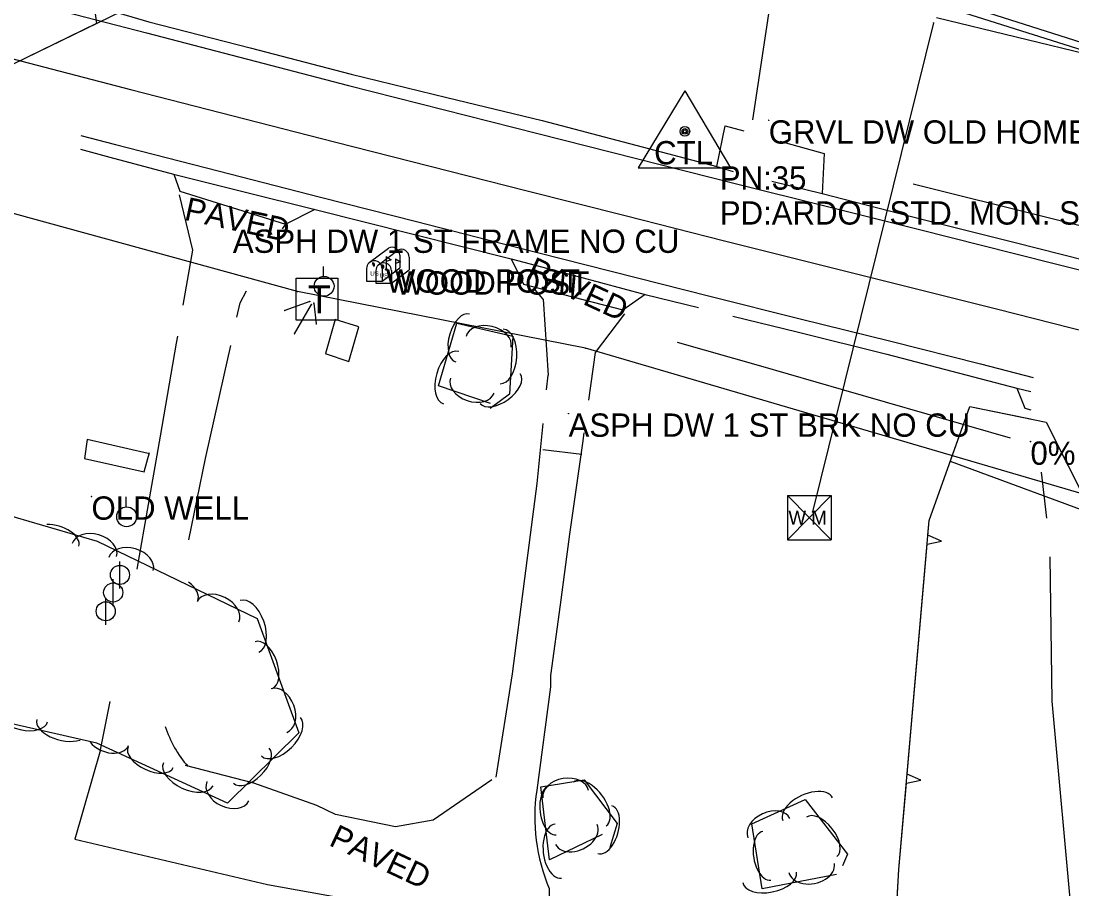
# Model space of a CAD drawing. Extents: x 954793 to 988390, y 1867850 to 1924428.
# Drawn here: x 963576.6 to 963802.1, y 1900745.2 to 1900931.5 of the extents above; entities that cross this region are included whole.
import ezdxf

# ---------------------------------------------------------------- set-up
doc = ezdxf.new("R2010")
doc.units = 0
for name, color, linetype in [('S_CROSS_DRAIN_ANNOT', 7, 'Continuous'), ('S_DITCHLINE', 7, 'Continuous'), ('S_DRG_PT_SYM', 7, 'Continuous'), ('S_DRIVEWAY', 7, 'Continuous'), ('S_EDGE_BITUMINOUS', 7, 'Continuous'), ('S_EDGE_PAVEMENT', 7, 'Continuous'), ('S_FIBER_OPTIC_CABLE', 7, 'Continuous'), ('S_MAILBOX', 7, 'Continuous'), ('S_MAILBOX_ANNOT', 7, 'Continuous'), ('S_MISC_STRUCTURES', 7, 'Continuous'), ('S_MSC_PT_SYM', 7, 'Continuous'), ('S_PARKING', 7, 'Continuous'), ('S_PARKING_ANNOT', 7, 'Continuous'), ('S_PAVEMENT_CROWN', 7, 'Continuous'), ('S_PRIMARY_CTL', 7, 'Continuous'), ('S_PRIMARY_CTL_ANNOT', 7, 'Continuous'), ('S_SHOULDER', 7, 'Continuous'), ('S_SIDEWALK', 7, 'Continuous'), ('S_STREAM', 7, 'Continuous'), ('S_SURVEY_TEXT_ANNOT', 7, 'Continuous'), ('S_TELEPHONE_UTILITIES', 7, 'Continuous'), ('S_TRAILS', 7, 'Continuous'), ('S_TREE', 7, 'Continuous'), ('S_UTILITY_POLE', 7, 'Continuous'), ('S_UTL_PT_SYM', 7, 'Continuous'), ('S_WATER_UTILITIES', 7, 'Continuous')]:
    doc.layers.add(name, color=color, linetype=linetype)

msp = doc.modelspace()

# ---------------------------------------------------------------- linework, layer by layer
at = {"layer": 'S_DITCHLINE'}
msp.add_lwpolyline([(963788.94, 1900841.95), (963771.08, 1900847.1), (963753.21, 1900852.24), (963735.35, 1900857.38), (963717.49, 1900862.52)], dxfattribs=at)
at = {"layer": 'S_DRG_PT_SYM'}
msp.add_lwpolyline([(963793.23, 1900841.24), (963793.23, 1900841.29), (963793.23, 1900841.24), (963793.18, 1900841.24), (963793.23, 1900841.24), (963793.23, 1900841.19), (963793.23, 1900841.24), (963793.28, 1900841.24)], dxfattribs=at)
at = {"layer": 'S_DRIVEWAY'}
for p, q in [((963678.6, 1900769.21), (963682.07, 1900791.4)), ((963689.94, 1900745.3), (963689.82, 1900732.7))]:
    msp.add_line(p, q, dxfattribs=at)
for points in [[(963610.53, 1900894.17), (963613.41, 1900882.29), (963611.35, 1900870.52)], [(963688.68, 1900871.79), (963686.96, 1900873.81)], [(963622.94, 1900867.95), (963623.61, 1900871)], [(963706.08, 1900868.66), (963699.83, 1900860.34), (963698.39, 1900850.13)], [(963610.18, 1900863.81), (963609.92, 1900862.34), (963606.43, 1900842.39), (963602.93, 1900822.45), (963601.43, 1900813.86)], [(963612.64, 1900820.11), (963616.22, 1900837.57), (963620.19, 1900855.49), (963621.59, 1900861.85)], [(963689.38, 1900852.32), (963689.7, 1900855.49)], [(963682.07, 1900791.4), (963684.71, 1900811.83), (963687.35, 1900832.26), (963688.65, 1900845.13)], [(963697.39, 1900843.07), (963697.08, 1900840.85), (963694.33, 1900821.36), (963692.3, 1900806.18), (963690.26, 1900791)], [(963690.26, 1900791), (963690.24, 1900788.61), (963687.26, 1900766.42)], [(963593.65, 1900775.09), (963588.15, 1900755.93), (963629.47, 1900746.18), (963651.41, 1900742.27), (963660.42, 1900737.2)], [(963677.61, 1900768.67), (963665.05, 1900760.02), (963656.93, 1900758.58), (963644.11, 1900761.23), (963640.08, 1900763.12), (963626.59, 1900767.94), (963611.88, 1900771.75)]]:
    msp.add_lwpolyline(points, dxfattribs=at)
msp.add_ellipse((963726.49, 1900760.74), major_axis=(-4.97, -39.48), ratio=0.996236, start_param=4.693811, end_param=5.23562, dxfattribs=at)
at = {"layer": 'S_EDGE_BITUMINOUS'}
for points in [[(963725.92, 1900900.28), (963727.72, 1900909), (963731.73, 1900907.87)], [(963739.46, 1900905.69), (963748.98, 1900903.01), (963748.52, 1900894.48)], [(963609.41, 1900898.64), (963610.67, 1900894.96), (963633.39, 1900887.86), (963639.69, 1900891.08)], [(963681.79, 1900880.42), (963684.46, 1900875.03), (963705.73, 1900869.47), (963710.56, 1900872.88)], [(963790.3, 1900852.69), (963792.05, 1900848.4), (963793.31, 1900848.06)]]:
    msp.add_lwpolyline(points, dxfattribs=at)
at = {"layer": 'S_EDGE_PAVEMENT'}
for points in [[(963564.17, 1900939.03), (963583.84, 1900933.98), (963603.52, 1900928.94), (963625.22, 1900923.29), (963646.91, 1900917.64), (963667.21, 1900912.48), (963687.51, 1900907.31), (963708.69, 1900901.95), (963729.87, 1900896.59), (963749.64, 1900891.65), (963769.42, 1900886.71), (963789.55, 1900881.66), (963809.68, 1900876.6)], [(963589.44, 1900906.92), (963596.89, 1900905), (963618.88, 1900899.33), (963640.86, 1900893.66), (963661.47, 1900888.43), (963682.07, 1900883.19), (963703.23, 1900877.82), (963724.39, 1900872.44), (963743.82, 1900867.6), (963763.24, 1900862.77), (963782.5, 1900857.88), (963793.84, 1900855)]]:
    msp.add_lwpolyline(points, dxfattribs=at)
at = {"layer": 'S_FIBER_OPTIC_CABLE'}
for p, q in [((964278.11, 1900775.13), (963743.78, 1900946.13)), ((964280.9, 1900773.98), (963742.61, 1900944.77)), ((963635.92, 1900873.41), (963480.96, 1900915.92)), ((963697.76, 1900861.28), (963635.92, 1900873.41)), ((963638.55, 1900871.29), (963633.18, 1900869.35)), ((963635.27, 1900864.38), (963638.94, 1900870.66)), ((963639.41, 1900870.93), (963639.97, 1900866.46)), ((963824.31, 1900824.17), (963697.76, 1900861.28)), ((963828.41, 1900817.62), (963776.07, 1900836.95))]:
    msp.add_line(p, q, dxfattribs=at)
at = {"layer": 'S_MAILBOX'}
for p, q in [((963651.32, 1900879.62), (963655.45, 1900882.73)), ((963653.33, 1900879.18), (963657.46, 1900882.29)), ((963654.93, 1900880.91), (963654.93, 1900878.19)), ((963656.94, 1900880.47), (963656.94, 1900877.76)), ((963657.88, 1900881.25), (963657.88, 1900878.54)), ((963659.89, 1900880.82), (963659.89, 1900878.1)), ((963650.76, 1900878.35), (963650.76, 1900875.63)), ((963652.77, 1900877.91), (963652.77, 1900875.19)), ((963654.09, 1900875.63), (963657.88, 1900878.54)), ((963654.09, 1900878.35), (963654.09, 1900875.63)), ((963656.1, 1900875.19), (963659.89, 1900878.1)), ((963656.1, 1900877.91), (963656.1, 1900875.19)), ((963650.76, 1900875.63), (963654.09, 1900875.63)), ((963652.77, 1900875.19), (963656.1, 1900875.19))]:
    msp.add_line(p, q, dxfattribs=at)
for points in [[(963654.93, 1900880.91), (963656.04, 1900880.24), (963654.93, 1900879.9)], [(963656.94, 1900880.47), (963658.05, 1900879.81), (963656.94, 1900879.46)], [(963651.95, 1900879.46), (963652.17, 1900879.32), (963652.17, 1900878.93), (963652.47, 1900878.93), (963652.47, 1900879.29), (963652.28, 1900879.54), (963651.95, 1900879.49)], [(963653.96, 1900879.02), (963654.18, 1900878.88), (963654.18, 1900878.5), (963654.48, 1900878.5), (963654.48, 1900878.86), (963654.29, 1900879.11), (963653.96, 1900879.05)]]:
    msp.add_lwpolyline(points, dxfattribs=at)
for centre, end in [((963656.22, 1900881.25), 117.5718), ((963658.23, 1900880.82), 117.5718), ((963652.43, 1900878.35), 180), ((963654.43, 1900877.91), 180)]:
    msp.add_arc(centre, 1.66, 0, end, dxfattribs=at)
for centre in [(963654.93, 1900878.19), (963656.94, 1900877.76)]:
    msp.add_ellipse(centre, major_axis=(0.145, 0.132), ratio=0.564646, dxfattribs=at)
at = {"layer": 'S_MISC_STRUCTURES'}
msp.add_lwpolyline([(963641.88, 1900860.14), (963646.98, 1900858.4), (963649.08, 1900865.85), (963643.99, 1900867.42), (963641.95, 1900860.14)], dxfattribs=at)
at = {"layer": 'S_MSC_PT_SYM'}
for points in [[(963737.06, 1900910.16), (963737.06, 1900910.21), (963737.06, 1900910.16), (963737.01, 1900910.16), (963737.06, 1900910.16), (963737.06, 1900910.11), (963737.06, 1900910.16), (963737.11, 1900910.16)], [(963622.05, 1900886.72), (963622.05, 1900886.77), (963622.05, 1900886.72), (963622, 1900886.72), (963622.05, 1900886.72), (963622.05, 1900886.67), (963622.05, 1900886.72), (963622.1, 1900886.72)], [(963694.11, 1900847.26), (963694.11, 1900847.31), (963694.11, 1900847.26), (963694.06, 1900847.26), (963694.11, 1900847.26), (963694.11, 1900847.21), (963694.11, 1900847.26), (963694.16, 1900847.26)], [(963591.72, 1900829.46), (963591.72, 1900829.51), (963591.72, 1900829.46), (963591.67, 1900829.46), (963591.72, 1900829.46), (963591.72, 1900829.41), (963591.72, 1900829.46), (963591.77, 1900829.46)]]:
    msp.add_lwpolyline(points, dxfattribs=at)
at = {"layer": 'S_PARKING'}
for p, q in [((963633.39, 1900887.86), (963632.67, 1900886.9)), ((963623.61, 1900871), (963625, 1900873.54)), ((963688.68, 1900871.79), (963689.7, 1900855.49)), ((963796.77, 1900824.76), (963795.63, 1900834.66))]:
    msp.add_line(p, q, dxfattribs=at)
for points in [[(963696.92, 1900838.42), (963688.58, 1900839.49)], [(963810.2, 1900814.41), (963810.2, 1900813.25), (963812.44, 1900775.03), (963816.58, 1900735.43), (963822.8, 1900714.82), (963834.09, 1900691.03), (963833.12, 1900680.93), (963807.8, 1900685.36), (963810.33, 1900704.24), (963802.22, 1900737.62), (963797.92, 1900785.51), (963797.43, 1900816.5)], [(963593.65, 1900775.09), (963595.76, 1900785.48)]]:
    msp.add_lwpolyline(points, dxfattribs=at)
msp.add_ellipse((963630.03, 1900787.22), major_axis=(13.66, -19.28), ratio=0.997823, start_param=4.403502, end_param=4.825122, dxfattribs=at)
at = {"layer": 'S_PAVEMENT_CROWN'}
msp.add_lwpolyline([(963559.23, 1900927.43), (963579.79, 1900922.06), (963600.35, 1900916.69), (963622.13, 1900911.12), (963643.9, 1900905.56), (963664.4, 1900900.33), (963684.9, 1900895.11), (963706.23, 1900889.71), (963727.56, 1900884.31), (963746.73, 1900879.52), (963765.9, 1900874.72), (963785.91, 1900869.69), (963805.93, 1900864.66)], dxfattribs=at)
msp.add_lwpolyline([(963559.23, 1900927.43), (963579.79, 1900922.06), (963600.35, 1900916.69), (963622.13, 1900911.12), (963643.9, 1900905.56), (963664.4, 1900900.33), (963684.9, 1900895.11), (963706.23, 1900889.71), (963727.56, 1900884.31), (963746.73, 1900879.52), (963765.9, 1900874.72), (963785.91, 1900869.69), (963805.93, 1900864.66)], dxfattribs=at)
at = {"layer": 'S_PRIMARY_CTL'}
for p, q in [((963719.06, 1900916.49), (963709.02, 1900899.98)), ((963719.06, 1900916.49), (963728.88, 1900899.98)), ((963709.02, 1900899.98), (963728.88, 1900899.98))]:
    msp.add_line(p, q, dxfattribs=at)
for radius in [1.04, 0.609, 0.344]:
    msp.add_circle((963719.06, 1900907.79), radius, dxfattribs=at)
at = {"layer": 'S_SHOULDER'}
for points in [[(963564.69, 1900941.47), (963580.41, 1900937.71), (963595.04, 1900933.94), (963604.02, 1900931.29), (963625.75, 1900925.69), (963647.48, 1900920.08), (963667.95, 1900915.08), (963688.42, 1900910.09), (963707.16, 1900905.19), (963725.91, 1900900.28), (963729.43, 1900899.2)], [(963589.33, 1900903.96), (963595.68, 1900902.28), (963609.34, 1900898.63), (963624.52, 1900894.83), (963639.7, 1900891.03), (963660.74, 1900885.73), (963681.79, 1900880.42), (963696.18, 1900876.62), (963710.57, 1900872.81), (963722, 1900869.99)], [(963737.74, 1900897.13), (963748.53, 1900894.49), (963769.94, 1900888.97), (963789.97, 1900883.91), (963810, 1900878.85)], [(963729.34, 1900868.17), (963743.16, 1900864.75), (963762.44, 1900859.97), (963776.36, 1900856.34), (963790.29, 1900852.71), (963793.34, 1900851.95)]]:
    msp.add_lwpolyline(points, dxfattribs=at)
at = {"layer": 'S_SIDEWALK'}
msp.add_lwpolyline([(963603.91, 1900838.67), (963590.78, 1900841.69), (963590.2, 1900837.62), (963602.99, 1900834.74), (963604.14, 1900838.87)], dxfattribs=at)
at = {"layer": 'S_STREAM'}
msp.add_lwpolyline([(963768.06, 1900896.54), (963826.32, 1900882.03), (963832.43, 1900880.74)], dxfattribs=at)
at = {"layer": 'S_TELEPHONE_UTILITIES'}
msp.add_lwpolyline([(963635.61, 1900867.27), (963635.61, 1900876.27), (963644.61, 1900876.27), (963644.61, 1900867.27)], close=True, dxfattribs=at)
at = {"layer": 'S_TRAILS'}
msp.add_lwpolyline([(963720.68, 1901102.93), (963729.86, 1901078.57), (963737.12, 1901041.67), (963736.82, 1901010.17), (963736.19, 1900972.39), (963737.02, 1900932.99), (963733.56, 1900910.27)], dxfattribs=at)
at = {"layer": 'S_TREE'}
for p, q in [((963592.4, 1900934.07), (963592.8, 1900930.93)), ((963771.06, 1900819.22), (963774.12, 1900819.87)), ((963774.12, 1900819.87), (963771.22, 1900821.16)), ((963769.67, 1900768.56), (963766.77, 1900769.84)), ((963766.6, 1900767.9), (963769.67, 1900768.56))]:
    msp.add_line(p, q, dxfattribs=at)
for points in [[(963593.06, 1901158.38), (963597.9, 1901116.56), (963596.77, 1901047.88), (963596.62, 1900991.14), (963603.49, 1900936.15), (963574.91, 1900922.19), (963539.92, 1900933.03), (963505.81, 1900939.53), (963471.1, 1900947.23), (963427.36, 1900958.35), (963392.3, 1900970.25), (963356.69, 1900978.51), (963321.15, 1900992.3), (963283.58, 1900997.98), (963244.17, 1901010.8), (963207.46, 1901025.63), (963182.04, 1901038.21), (963172.79, 1901077.33), (963175.9, 1901108.5), (963173.49, 1901146.91), (963169.8, 1901185.3), (963175.44, 1901218.15), (963182.78, 1901243.46), (963185.42, 1901259.74)], [(963592.8, 1900930.93), (963574.91, 1900922.19), (963570.05, 1900923.69)], [(963310.87, 1900871.52), (963343.77, 1900871.48), (963381.86, 1900862.53), (963433.39, 1900854.55), (963479.46, 1900841.97), (963526.99, 1900833.45), (963563.51, 1900828.43), (963592.96, 1900819.88), (963627.3, 1900803.28), (963636.22, 1900778.71), (963620.89, 1900763.62), (963592.86, 1900776.51), (963567.32, 1900782.28), (963535.49, 1900793.28), (963503.46, 1900804.3), (963467.8, 1900802.55), (963427.4, 1900811.77), (963387.69, 1900819.14), (963351.32, 1900824.27), (963321.34, 1900826.96), (963298.82, 1900836.32)], [(963677.35, 1900849.38), (963666.2, 1900853.2), (963670.09, 1900866.66), (963682.13, 1900863.86), (963681.41, 1900851.41), (963677.25, 1900848.35)], [(963754.65, 1900639.74), (963763.16, 1900717.3), (963765, 1900749.37), (963771.5, 1900824.31), (963780.25, 1900848.78), (963796.63, 1900845.39), (963806.05, 1900826.62)], [(963778.66, 1900844.33), (963780.25, 1900848.78), (963793.27, 1900846.09)], [(963771.22, 1900821.16), (963771.5, 1900824.31), (963778.66, 1900844.33)], [(963768.91, 1900794.53), (963771.06, 1900819.22)], [(963766.77, 1900769.84), (963768.91, 1900794.53)], [(963701.28, 1900756.94), (963689.98, 1900751.46), (963688.13, 1900767.11), (963697.42, 1900768.61), (963704.5, 1900759.24), (963702.98, 1900754.1)], [(963764.64, 1900743.15), (963765, 1900749.37), (963766.6, 1900767.9)], [(963751.58, 1900748.34), (963735.68, 1900745.28), (963733.43, 1900759.2), (963744.87, 1900764.41), (963753.94, 1900752.71), (963752.91, 1900750.22)]]:
    msp.add_lwpolyline(points, dxfattribs=at)
for centre, major_axis, ratio, start_param, end_param in [((963671.37, 1900863.46), (-1.49, -5.14), 0.540702, 3.141593, 6.283185), ((963676.93, 1900862.62), (-4.83, 1.12), 0.685311, 3.141593, 6.283185), ((963679.75, 1900859.51), (0.34, 5.86), 0.55008, 3.141593, 6.283185), ((963668.91, 1900854.94), (-1.63, -5.64), 0.550083, 3.141593, 6.283185), ((963679.44, 1900852.6), (4.31, 3.17), 0.540699, 3.141593, 6.283185), ((963673.43, 1900853.24), (4.69, -1.6), 0.685373, 3.141593, 6.283185), ((963583.9, 1900820.3), (-5.13, 1.49), 0.540699, 3.141593, 5.217567), ((963592.36, 1900817.95), (-4.76, 1.38), 0.685311, 3.141593, 6.283185), ((963600.22, 1900814.95), (-4.76, 1.38), 0.685311, 3.141593, 6.283185), ((963609.7, 1900809.44), (-4.81, 2.33), 0.540699, 3.141593, 4.354073), ((963618.86, 1900804.72), (-4.46, 2.16), 0.685311, 3.141593, 6.283185), ((963625.66, 1900801.59), (-2, 5.52), 0.55008, 3.141593, 6.283185), ((963628.68, 1900793.25), (-1.82, 5.03), 0.540699, 3.141593, 6.283185), ((963631.95, 1900783.48), (-1.69, 4.66), 0.685311, 3.141593, 6.283185), ((963577.05, 1900782.25), (5.22, -1.18), 0.540699, 3.141593, 6.283185), ((963585.7, 1900780.3), (5.72, -1.29), 0.55008, 3.141593, 5.500543), ((963632.36, 1900777.89), (4.18, 4.12), 0.55008, 3.141593, 6.283185), ((963595.17, 1900778.07), (4.5, -2.07), 0.685311, 4.112373, 6.283185), ((963604.42, 1900773.53), (4.86, -2.23), 0.540699, 3.141593, 6.283185), ((963626.04, 1900771.67), (3.81, 3.75), 0.540699, 3.141593, 6.283185), ((963612.47, 1900769.82), (5.33, -2.45), 0.55008, 3.141593, 6.283185), ((963620.99, 1900766.19), (4.5, -2.07), 0.685311, 3.141593, 6.283185), ((963690.85, 1900762.14), (0.63, -5.3), 0.541073, 3.140636, 6.282229), ((963693.48, 1900765.57), (-4.89, -0.79), 0.685043, 3.141593, 6.283185), ((963698.67, 1900763.44), (-3.53, 4.68), 0.54968, 3.141572, 6.283165), ((963745.43, 1900762.34), (-5.34, -2.43), 0.546818, 3.141755, 6.283348), ((963701.9, 1900757.92), (1.51, 5.12), 0.541656, 3.140962, 6.282555), ((963737.11, 1900758.28), (-4.51, -2.05), 0.681247, 3.141858, 6.28345), ((963748.43, 1900756.38), (-3.28, 4.22), 0.53668, 3.141593, 6.283185), ((963691.89, 1900753.34), (0.69, -5.82), 0.55046, 3.140605, 6.282198), ((963695.78, 1900756.92), (4.46, 2.16), 0.685265, 3.141944, 6.283537), ((963736.68, 1900752.35), (0.87, -5.23), 0.544137, 3.134804, 6.276397), ((963746.27, 1900749.72), (4.87, 0.94), 0.679619, 3.140298, 6.281891), ((963737.23, 1900747.72), (5.76, 1.11), 0.545511, 3.140797, 6.282389)]:
    msp.add_ellipse(centre, major_axis=major_axis, ratio=ratio, start_param=start_param, end_param=end_param, dxfattribs=at)
at = {"layer": 'S_UTILITY_POLE'}
for p, q in [((963641.51, 1900876.69), (963641.51, 1900878.8)), ((963599.15, 1900827.23), (963599.15, 1900829.34)), ((963597.83, 1900809.69), (963597.83, 1900815.48)), ((963596.38, 1900805.91), (963596.38, 1900811.7)), ((963594.78, 1900801.88), (963594.78, 1900807.67))]:
    msp.add_line(p, q, dxfattribs=at)
for centre, radius in [((963641.64, 1900874.55), 2.13), ((963599.27, 1900825.09), 2.13), ((963597.83, 1900812.62), 2.05), ((963596.38, 1900808.84), 2.05), ((963594.78, 1900804.81), 2.05)]:
    msp.add_circle(centre, radius, dxfattribs=at)
at = {"layer": 'S_UTL_PT_SYM'}
for points in [[(963772.45, 1900931.1), (963772.45, 1900931.15), (963772.45, 1900931.1), (963772.4, 1900931.1), (963772.45, 1900931.1), (963772.45, 1900931.05), (963772.45, 1900931.1), (963772.5, 1900931.1)], [(963635.92, 1900873.41), (963635.92, 1900873.46), (963635.92, 1900873.41), (963635.87, 1900873.41), (963635.92, 1900873.41), (963635.92, 1900873.36), (963635.92, 1900873.41), (963635.97, 1900873.41)], [(963638.55, 1900871.29), (963638.55, 1900871.34), (963638.55, 1900871.29), (963638.5, 1900871.29), (963638.55, 1900871.29), (963638.55, 1900871.24), (963638.55, 1900871.29), (963638.6, 1900871.29)], [(963633.18, 1900869.35), (963633.18, 1900869.4), (963633.18, 1900869.35), (963633.13, 1900869.35), (963633.18, 1900869.35), (963633.18, 1900869.3), (963633.18, 1900869.35), (963633.23, 1900869.35)], [(963638.94, 1900870.66), (963638.94, 1900870.71), (963638.94, 1900870.66), (963638.89, 1900870.66), (963638.94, 1900870.66), (963638.94, 1900870.61), (963638.94, 1900870.66), (963638.99, 1900870.66)], [(963639.41, 1900870.93), (963639.41, 1900870.98), (963639.41, 1900870.93), (963639.36, 1900870.93), (963639.41, 1900870.93), (963639.41, 1900870.88), (963639.41, 1900870.93), (963639.46, 1900870.93)], [(963639.97, 1900866.46), (963639.97, 1900866.51), (963639.97, 1900866.46), (963639.92, 1900866.46), (963639.97, 1900866.46), (963639.97, 1900866.41), (963639.97, 1900866.46), (963640.02, 1900866.46)], [(963635.27, 1900864.38), (963635.27, 1900864.43), (963635.27, 1900864.38), (963635.22, 1900864.38), (963635.27, 1900864.38), (963635.27, 1900864.33), (963635.27, 1900864.38), (963635.32, 1900864.38)], [(963697.76, 1900861.28), (963697.76, 1900861.33), (963697.76, 1900861.28), (963697.71, 1900861.28), (963697.76, 1900861.28), (963697.76, 1900861.23), (963697.76, 1900861.28), (963697.81, 1900861.28)], [(963776.07, 1900836.95), (963776.07, 1900837), (963776.07, 1900836.95), (963776.02, 1900836.95), (963776.07, 1900836.95), (963776.07, 1900836.9), (963776.07, 1900836.95), (963776.12, 1900836.95)], [(963746.44, 1900826.12), (963746.44, 1900826.17), (963746.44, 1900826.12), (963746.39, 1900826.12), (963746.44, 1900826.12), (963746.44, 1900826.07), (963746.44, 1900826.12), (963746.49, 1900826.12)]]:
    msp.add_lwpolyline(points, dxfattribs=at)
at = {"layer": 'S_WATER_UTILITIES'}
for p, q in [((963875.31, 1900907.33), (963773.09, 1900932.17)), ((963772.45, 1900931.1), (963746.44, 1900826.12)), ((963741.09, 1900829.65), (963750.43, 1900829.65)), ((963741.09, 1900829.65), (963741.09, 1900820.16)), ((963741.09, 1900829.65), (963750.43, 1900820.16)), ((963750.43, 1900829.65), (963741.09, 1900820.16)), ((963750.43, 1900829.65), (963750.43, 1900820.16)), ((963741.09, 1900820.16), (963750.43, 1900820.16))]:
    msp.add_line(p, q, dxfattribs=at)

# ---------------------------------------------------------------- texts
at = {"layer": 'S_CROSS_DRAIN_ANNOT'}
msp.add_text('0% FILL', height=5, dxfattribs=at).set_placement((963793.23, 1900836.24))
at = {"layer": 'S_MAILBOX'}
for p in [(963651.53, 1900876.82), (963653.54, 1900876.39)]:
    msp.add_text('US', height=0.96, rotation=360, dxfattribs=at).set_placement(p)
at = {"layer": 'S_MAILBOX_ANNOT'}
for p in [(963654.93, 1900873.19), (963656.94, 1900872.76)]:
    msp.add_text('WOOD POST', height=5, dxfattribs=at).set_placement(p)
at = {"layer": 'S_PARKING_ANNOT'}
for rotation, p in [(347.8317, (963611.43, 1900888.84)), (335.1441, (963684.8, 1900876.45)), (334.8186, (963642.46, 1900754.69))]:
    msp.add_text('PAVED', height=5, rotation=rotation, dxfattribs=at).set_placement(p)
at = {"layer": 'S_PRIMARY_CTL'}
msp.add_text('CTL', height=5, rotation=360, dxfattribs=at).set_placement((963712.47, 1900900.71))
at = {"layer": 'S_PRIMARY_CTL_ANNOT'}
for s, p in [('PN:35', (963726.56, 1900895.29)), ('PD:ARDOT STD. MON. STAMPED PN:35', (963726.56, 1900887.79))]:
    msp.add_text(s, height=5, dxfattribs=at).set_placement(p)
at = {"layer": 'S_SURVEY_TEXT_ANNOT'}
for s, p in [('GRVL DW OLD HOME SITE NO CU', (963737.06, 1900905.16)), ('ASPH DW 1 ST FRAME NO CU', (963622.05, 1900881.72)), ('ASPH DW 1 ST BRK NO CU', (963694.11, 1900842.26)), ('OLD WELL', (963591.72, 1900824.46))]:
    msp.add_text(s, height=5, dxfattribs=at).set_placement(p)
at = {"layer": 'S_TELEPHONE_UTILITIES'}
msp.add_text('T', height=6, rotation=360, dxfattribs=at).set_placement((963638.17, 1900868.77))
at = {"layer": 'S_WATER_UTILITIES'}
msp.add_text('W M', height=3, rotation=360, dxfattribs=at).set_placement((963741.29, 1900823.42))

doc.saveas('drawing.dxf')
